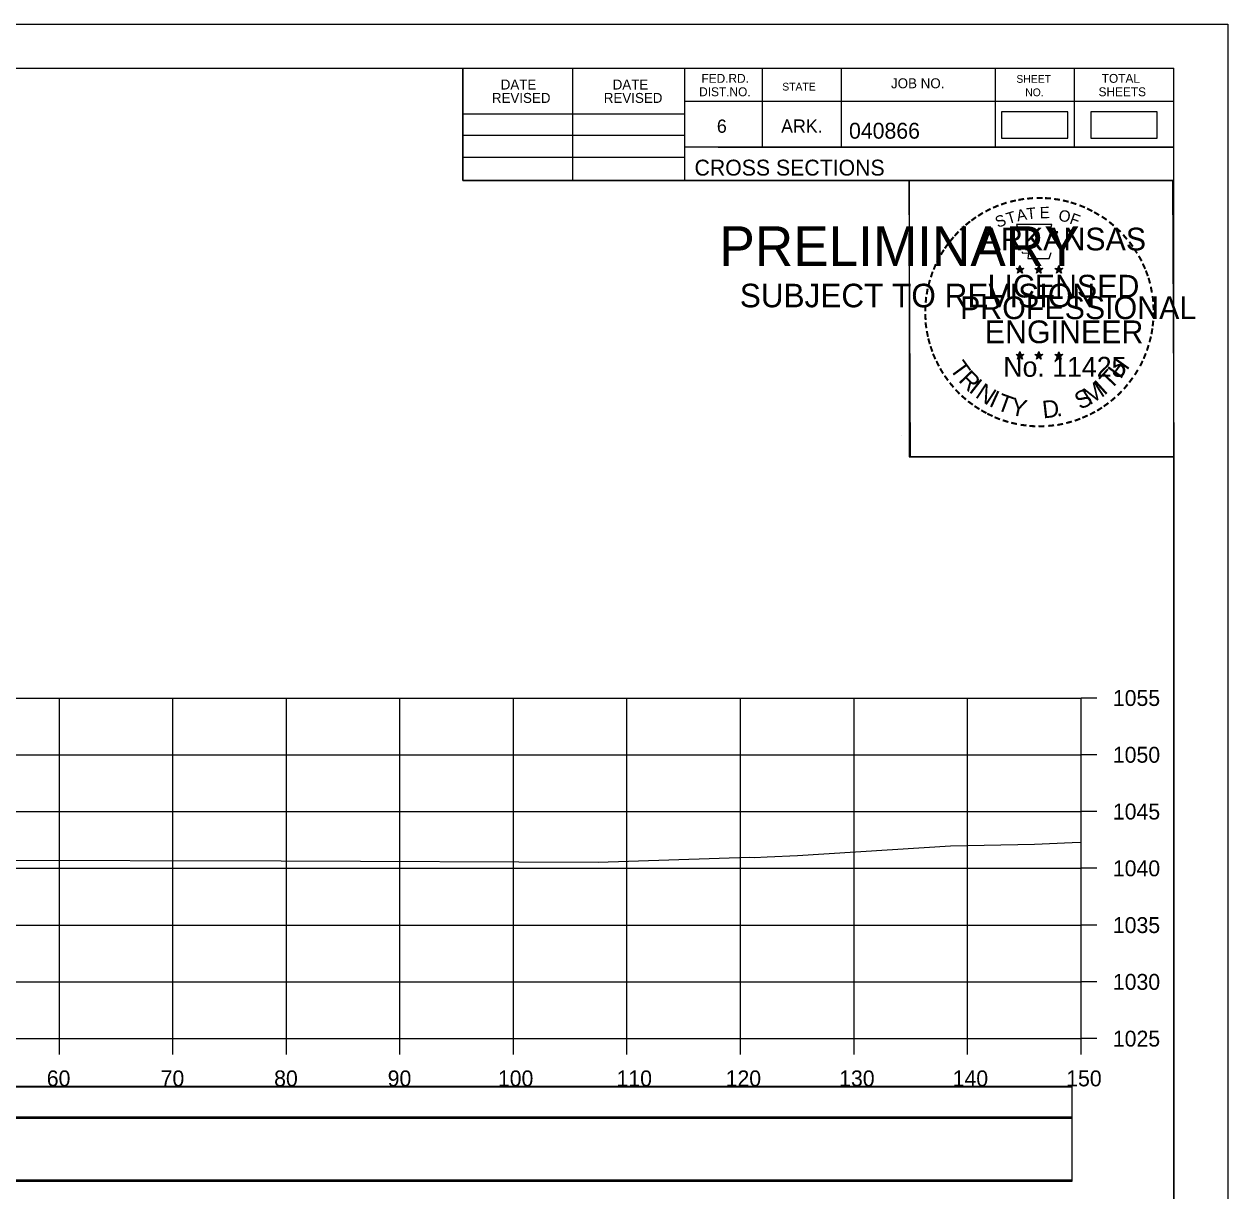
# Model space of a CAD drawing. Extents: x 1370565 to 1374448, y 301010 to 304637.
# Drawn here: x 1373425.7 to 1373531.7, y 301408.9 to 301511.7 of the extents above; entities that cross this region are included whole.
import ezdxf

# ---------------------------------------------------------------- set-up
doc = ezdxf.new("R2010")
doc.units = 0
for name, color, linetype in [('Default', 7, 'Continuous'), ('R_Axis', 7, 'Continuous'), ('R_Axis Annot', 7, 'Continuous'), ('R_Border', 7, 'Continuous'), ('R_Border PE', 7, 'Continuous'), ('R_Border Prem', 7, 'Continuous'), ('R_Drive', 7, 'Continuous'), ('R_Exist Surface', 7, 'Continuous'), ('R_Grid', 7, 'Continuous'), ('R_No Plot', 7, 'Continuous')]:
    doc.layers.add(name, color=color, linetype=linetype)

msp = doc.modelspace()

# ---------------------------------------------------------------- linework, layer by layer
at = {"layer": 'Default'}
for points in [[(1373511.81, 301501.6), (1373517.64, 301501.6), (1373517.64, 301503.91), (1373511.81, 301503.91)], [(1373219.61, 301415.34), (1373518.02, 301415.34), (1373518.02, 301418.04), (1373219.61, 301418.04)], [(1373219.61, 301409.76), (1373518.02, 301409.76), (1373518.02, 301415.28), (1373219.61, 301415.28)]]:
    msp.add_lwpolyline(points, close=True, dxfattribs=at)
at = {"layer": 'R_Axis'}
for p, q in [((1373518.81, 301422.3), (1373518.81, 301452.3)), ((1373520.21, 301452.3), (1373518.81, 301452.3)), ((1373520.21, 301447.3), (1373518.81, 301447.3)), ((1373520.21, 301442.3), (1373518.81, 301442.3)), ((1373520.21, 301437.3), (1373518.81, 301437.3)), ((1373520.21, 301432.3), (1373518.81, 301432.3)), ((1373520.21, 301427.3), (1373518.81, 301427.3)), ((1373218.81, 301422.3), (1373518.81, 301422.3)), ((1373428.81, 301420.9), (1373428.81, 301422.3)), ((1373438.81, 301420.9), (1373438.81, 301422.3)), ((1373448.81, 301420.9), (1373448.81, 301422.3)), ((1373458.81, 301420.9), (1373458.81, 301422.3)), ((1373468.81, 301420.9), (1373468.81, 301422.3)), ((1373478.81, 301420.9), (1373478.81, 301422.3)), ((1373488.81, 301420.9), (1373488.81, 301422.3)), ((1373498.81, 301420.9), (1373498.81, 301422.3)), ((1373508.81, 301420.9), (1373508.81, 301422.3)), ((1373518.81, 301420.9), (1373518.81, 301422.3)), ((1373520.21, 301422.3), (1373518.81, 301422.3))]:
    msp.add_line(p, q, dxfattribs=at)
at = {"layer": 'R_Border'}
for p, q in [((1373210.81, 301507.76), (1373526.99, 301507.76)), ((1373464.35, 301497.88), (1373464.35, 301507.76)), ((1373474.03, 301497.88), (1373474.03, 301507.76)), ((1373483.89, 301507.76), (1373483.89, 301497.88)), ((1373490.73, 301507.76), (1373490.73, 301500.82)), ((1373497.67, 301507.76), (1373497.67, 301500.82)), ((1373511.25, 301507.76), (1373511.25, 301500.82)), ((1373518.19, 301507.76), (1373518.19, 301500.82)), ((1373526.99, 301302.3), (1373526.99, 301507.76)), ((1373526.99, 301504.82), (1373483.89, 301504.82)), ((1373526.99, 301504.84), (1373526.99, 301504.84)), ((1373464.35, 301503.74), (1373483.89, 301503.74)), ((1373464.35, 301501.88), (1373483.89, 301501.88)), ((1373526.99, 301500.82), (1373483.89, 301500.82)), ((1373486.85, 301500.82), (1373526.99, 301500.82)), ((1373464.35, 301499.94), (1373483.89, 301499.94)), ((1373526.99, 301497.88), (1373464.35, 301497.88))]:
    msp.add_line(p, q, dxfattribs=at)
at = {"layer": 'R_Border PE'}
for p, q in [((1373513.08, 301490.13), (1373513.43, 301490.02)), ((1373513.08, 301490.13), (1373513.33, 301490.09)), ((1373513.08, 301490.13), (1373513.32, 301490.01)), ((1373513.21, 301489.73), (1373513.43, 301490.02)), ((1373513.21, 301489.73), (1373513.34, 301489.97)), ((1373513.21, 301489.73), (1373513.43, 301489.94)), ((1373513.43, 301490.39), (1373513.39, 301490.14)), ((1373513.43, 301490.02), (1373513.43, 301490.39)), ((1373513.43, 301490.39), (1373513.48, 301490.14)), ((1373513.78, 301490.13), (1373513.43, 301490.02)), ((1373513.64, 301489.73), (1373513.43, 301490.02)), ((1373513.64, 301489.73), (1373513.43, 301489.94)), ((1373513.78, 301490.13), (1373513.49, 301490.08)), ((1373513.64, 301489.73), (1373513.5, 301490.02)), ((1373513.78, 301490.13), (1373513.57, 301490.03)), ((1373514.75, 301490.13), (1373515.1, 301490.02)), ((1373514.75, 301490.13), (1373515, 301490.09)), ((1373514.75, 301490.13), (1373514.99, 301490.01)), ((1373514.88, 301489.73), (1373515.1, 301490.02)), ((1373514.88, 301489.73), (1373515.01, 301489.97)), ((1373514.88, 301489.73), (1373515.1, 301489.94)), ((1373515.1, 301490.39), (1373515.06, 301490.14)), ((1373515.1, 301490.02), (1373515.1, 301490.39)), ((1373515.1, 301490.39), (1373515.15, 301490.14)), ((1373515.45, 301490.13), (1373515.1, 301490.02)), ((1373515.31, 301489.73), (1373515.1, 301490.02)), ((1373515.31, 301489.73), (1373515.1, 301489.94)), ((1373515.45, 301490.13), (1373515.16, 301490.08)), ((1373515.31, 301489.73), (1373515.17, 301490.02)), ((1373515.45, 301490.13), (1373515.24, 301490.03)), ((1373516.51, 301490.12), (1373516.86, 301490.01)), ((1373516.51, 301490.12), (1373516.77, 301490.08)), ((1373516.51, 301490.12), (1373516.75, 301490)), ((1373516.65, 301489.71), (1373516.86, 301490.01)), ((1373516.65, 301489.71), (1373516.77, 301489.96)), ((1373516.65, 301489.71), (1373516.86, 301489.93)), ((1373516.86, 301490.38), (1373516.82, 301490.12)), ((1373516.86, 301490.01), (1373516.86, 301490.38)), ((1373516.86, 301490.38), (1373516.91, 301490.13)), ((1373517.21, 301490.12), (1373516.86, 301490.01)), ((1373517.08, 301489.71), (1373516.86, 301490.01)), ((1373517.08, 301489.71), (1373516.86, 301489.93)), ((1373517.21, 301490.12), (1373516.92, 301490.07)), ((1373517.08, 301489.71), (1373516.94, 301490)), ((1373517.21, 301490.12), (1373517.01, 301490.02)), ((1373513.08, 301482.56), (1373513.42, 301482.45)), ((1373513.08, 301482.56), (1373513.33, 301482.52)), ((1373513.08, 301482.56), (1373513.31, 301482.44)), ((1373513.21, 301482.15), (1373513.42, 301482.45)), ((1373513.21, 301482.15), (1373513.33, 301482.4)), ((1373513.21, 301482.15), (1373513.42, 301482.37)), ((1373513.42, 301482.81), (1373513.38, 301482.56)), ((1373513.42, 301482.45), (1373513.42, 301482.81)), ((1373513.42, 301482.81), (1373513.47, 301482.56)), ((1373513.77, 301482.56), (1373513.42, 301482.45)), ((1373513.64, 301482.15), (1373513.42, 301482.45)), ((1373513.64, 301482.15), (1373513.42, 301482.37)), ((1373513.77, 301482.56), (1373513.49, 301482.51)), ((1373513.64, 301482.15), (1373513.5, 301482.44)), ((1373513.77, 301482.56), (1373513.57, 301482.46)), ((1373514.74, 301482.56), (1373515.09, 301482.45)), ((1373514.74, 301482.56), (1373515, 301482.52)), ((1373514.74, 301482.56), (1373514.98, 301482.44)), ((1373514.88, 301482.15), (1373515.09, 301482.45)), ((1373514.88, 301482.15), (1373515, 301482.4)), ((1373514.88, 301482.15), (1373515.09, 301482.37)), ((1373515.09, 301482.81), (1373515.05, 301482.56)), ((1373515.09, 301482.45), (1373515.09, 301482.81)), ((1373515.09, 301482.81), (1373515.14, 301482.56)), ((1373515.44, 301482.56), (1373515.09, 301482.45)), ((1373515.31, 301482.15), (1373515.09, 301482.45)), ((1373515.31, 301482.15), (1373515.09, 301482.37)), ((1373515.44, 301482.56), (1373515.15, 301482.51)), ((1373515.31, 301482.15), (1373515.17, 301482.44)), ((1373515.44, 301482.56), (1373515.24, 301482.46)), ((1373516.51, 301482.55), (1373516.86, 301482.44)), ((1373516.51, 301482.55), (1373516.76, 301482.51)), ((1373516.51, 301482.55), (1373516.75, 301482.43)), ((1373516.64, 301482.14), (1373516.86, 301482.44)), ((1373516.64, 301482.14), (1373516.77, 301482.39)), ((1373516.64, 301482.14), (1373516.86, 301482.36)), ((1373516.86, 301482.8), (1373516.82, 301482.55)), ((1373516.86, 301482.44), (1373516.86, 301482.8)), ((1373516.86, 301482.8), (1373516.91, 301482.55)), ((1373517.21, 301482.55), (1373516.86, 301482.44)), ((1373517.07, 301482.14), (1373516.86, 301482.44)), ((1373517.07, 301482.14), (1373516.86, 301482.36)), ((1373517.21, 301482.55), (1373516.92, 301482.5)), ((1373517.07, 301482.14), (1373516.94, 301482.43)), ((1373517.21, 301482.55), (1373517, 301482.45))]:
    msp.add_line(p, q, dxfattribs=at)
for points in [[(1373513.12, 301494.01), (1373513.39, 301493.18)], [(1373516.63, 301493.09), (1373516.77, 301493.37), (1373516.09, 301493.35), (1373516.24, 301494.01), (1373513.12, 301494.01)], [(1373513.61, 301491.59), (1373513.61, 301491.5), (1373514.18, 301491.48), (1373514.12, 301491.01), (1373515.99, 301491.01), (1373516.19, 301491.55)], [(1373513.43, 301490.39), (1373513.64, 301489.73), (1373513.08, 301490.13), (1373513.78, 301490.13), (1373513.21, 301489.73), (1373513.43, 301490.39)], [(1373515.1, 301490.39), (1373515.31, 301489.73), (1373514.75, 301490.13), (1373515.45, 301490.13), (1373514.88, 301489.73), (1373515.1, 301490.39)], [(1373516.86, 301490.38), (1373517.08, 301489.71), (1373516.51, 301490.12), (1373517.21, 301490.12), (1373516.65, 301489.71), (1373516.86, 301490.38)], [(1373513.42, 301482.81), (1373513.64, 301482.15), (1373513.08, 301482.56), (1373513.77, 301482.56), (1373513.21, 301482.15), (1373513.42, 301482.81)], [(1373515.09, 301482.81), (1373515.31, 301482.15), (1373514.74, 301482.56), (1373515.44, 301482.56), (1373514.88, 301482.15), (1373515.09, 301482.81)], [(1373516.86, 301482.8), (1373517.07, 301482.14), (1373516.51, 301482.55), (1373517.21, 301482.55), (1373516.64, 301482.14), (1373516.86, 301482.8)]]:
    msp.add_lwpolyline(points, dxfattribs=at)
for centre, radius in [((1373513.43, 301490.02), 0.172), ((1373513.43, 301490.02), 0.145), ((1373513.43, 301490.02), 0.116), ((1373513.43, 301490.02), 0.0991), ((1373513.43, 301490.02), 0.0747), ((1373513.43, 301490.02), 0.0495), ((1373513.43, 301490.02), 0.0296), ((1373515.1, 301490.02), 0.172), ((1373515.1, 301490.02), 0.145), ((1373515.1, 301490.02), 0.116), ((1373515.1, 301490.02), 0.0991), ((1373515.1, 301490.02), 0.0747), ((1373515.1, 301490.02), 0.0495), ((1373515.1, 301490.02), 0.0296), ((1373516.86, 301490.01), 0.172), ((1373516.86, 301490.01), 0.145), ((1373516.86, 301490.01), 0.116), ((1373516.86, 301490.01), 0.0991), ((1373516.86, 301490.01), 0.0747), ((1373516.86, 301490.01), 0.0495), ((1373516.86, 301490.01), 0.0296), ((1373513.42, 301482.45), 0.172), ((1373513.42, 301482.45), 0.145), ((1373513.42, 301482.45), 0.116), ((1373513.42, 301482.45), 0.0991), ((1373513.42, 301482.45), 0.0747), ((1373513.42, 301482.45), 0.0495), ((1373513.42, 301482.45), 0.0296), ((1373515.09, 301482.45), 0.172), ((1373515.09, 301482.45), 0.145), ((1373515.09, 301482.45), 0.116), ((1373515.09, 301482.45), 0.0991), ((1373515.09, 301482.45), 0.0747), ((1373515.09, 301482.45), 0.0495), ((1373515.09, 301482.45), 0.0296), ((1373516.86, 301482.44), 0.172), ((1373516.86, 301482.44), 0.145), ((1373516.86, 301482.44), 0.116), ((1373516.86, 301482.44), 0.0991), ((1373516.86, 301482.44), 0.0747), ((1373516.86, 301482.44), 0.0495), ((1373516.86, 301482.44), 0.0296)]:
    msp.add_circle(centre, radius, dxfattribs=at)
at = {"layer": 'R_Drive'}
for points in [[(1373519.68, 301501.61), (1373525.51, 301501.61), (1373525.51, 301503.92), (1373519.68, 301503.92)], [(1373219.61, 301415.39), (1373518.02, 301415.39), (1373518.02, 301418.1), (1373219.61, 301418.1)], [(1373219.61, 301409.87), (1373518.02, 301409.87), (1373518.02, 301415.39), (1373219.61, 301415.39)]]:
    msp.add_lwpolyline(points, close=True, dxfattribs=at)
at = {"layer": 'R_Exist Surface'}
msp.add_lwpolyline([(1373304.34, 301436.57), (1373342.67, 301437.61), (1373353.33, 301435.92), (1373354.89, 301435.65), (1373359.09, 301436.44), (1373372.67, 301438.99), (1373374.17, 301439.03), (1373383.25, 301439.29), (1373391.86, 301439.22), (1373393.43, 301439.2), (1373397.72, 301438.66), (1373412.1, 301436.72), (1373414.24, 301437.01), (1373421.68, 301438.02), (1373448.35, 301437.96), (1373476.27, 301437.85), (1373489.59, 301438.27), (1373490.01, 301438.26), (1373491.15, 301438.32), (1373493.83, 301438.43), (1373507.3, 301439.28), (1373514.72, 301439.44), (1373518.02, 301439.57), (1373518.81, 301439.61)], dxfattribs=at)
at = {"layer": 'R_Grid'}
for p, q in [((1373218.81, 301452.3), (1373518.81, 301452.3)), ((1373428.81, 301422.3), (1373428.81, 301452.3)), ((1373438.81, 301422.3), (1373438.81, 301452.3)), ((1373448.81, 301422.3), (1373448.81, 301452.3)), ((1373458.81, 301422.3), (1373458.81, 301452.3)), ((1373468.81, 301422.3), (1373468.81, 301452.3)), ((1373478.81, 301422.3), (1373478.81, 301452.3)), ((1373488.81, 301422.3), (1373488.81, 301452.3)), ((1373498.81, 301422.3), (1373498.81, 301452.3)), ((1373508.81, 301422.3), (1373508.81, 301452.3)), ((1373518.81, 301422.3), (1373518.81, 301452.3)), ((1373218.81, 301447.3), (1373518.81, 301447.3)), ((1373218.81, 301442.3), (1373518.81, 301442.3)), ((1373218.81, 301437.3), (1373518.81, 301437.3)), ((1373218.81, 301432.3), (1373518.81, 301432.3)), ((1373218.81, 301427.3), (1373518.81, 301427.3)), ((1373218.81, 301422.3), (1373518.81, 301422.3))]:
    msp.add_line(p, q, dxfattribs=at)
at = {"layer": 'R_No Plot'}
for p, q in [((1373198.41, 301511.65), (1373531.75, 301511.65)), ((1373503.03, 301475.42), (1373503.03, 301475.42))]:
    msp.add_line(p, q, dxfattribs=at)
for points in [[(1373198.41, 301511.65), (1373531.75, 301511.65), (1373531.75, 301298.32), (1373198.41, 301298.32)], [(1373444.73, 301507.76), (1373464.35, 301507.76), (1373464.35, 301497.88), (1373480.47, 301497.88), (1373503.67, 301497.88), (1373503.67, 301473.55), (1373526.99, 301473.55), (1373526.99, 301302.3), (1373210.81, 301302.3), (1373210.81, 301507.76)], [(1373503.67, 301497.88), (1373526.87, 301497.88), (1373526.99, 301473.55), (1373503.79, 301473.55)]]:
    msp.add_lwpolyline(points, close=True, dxfattribs=at)

# ---------------------------------------------------------------- texts
at = {"layer": 'R_Axis Annot'}
for s, p in [('1055', (1373521.61, 301451.6)), ('1050', (1373521.61, 301446.6)), ('1045', (1373521.61, 301441.6)), ('1040', (1373521.61, 301436.6)), ('1035', (1373521.61, 301431.6)), ('1030', (1373521.61, 301426.6)), ('1025', (1373521.61, 301421.6)), ('60', (1373427.7, 301418.1)), ('70', (1373437.73, 301418.1)), ('80', (1373447.73, 301418.1)), ('90', (1373457.73, 301418.1)), ('100', (1373467.44, 301418.1)), ('110', (1373477.89, 301418.1)), ('120', (1373487.5, 301418.1)), ('130', (1373497.5, 301418.1)), ('140', (1373507.5, 301418.1)), ('150', (1373517.5, 301418.1))]:
    msp.add_text(s, height=1.4, dxfattribs=at).set_placement(p)
at = {"layer": 'R_Border'}
for s, height, p in [('DATE', 0.879, (1373467.69, 301505.89)), ('DATE', 0.879, (1373477.55, 301505.89)), ('FED.RD.', 0.782, (1373485.37, 301506.48)), ('JOB NO.', 0.879, (1373502.07, 301506)), ('SHEET', 0.684, (1373513.11, 301506.48)), ('TOTAL', 0.782, (1373520.63, 301506.48)), ('REVISED', 0.879, (1373466.91, 301504.71)), ('REVISED', 0.879, (1373476.77, 301504.71)), ('DIST.NO.', 0.782, (1373485.17, 301505.3)), ('STATE', 0.684, (1373492.49, 301505.8)), ('NO.', 0.684, (1373513.89, 301505.3)), ('SHEETS', 0.782, (1373520.35, 301505.3)), ('6', 1.17, (1373486.73, 301502.08)), ('ARK.', 1.172, (1373492.39, 301502.08)), ('040866', 1.4, (1373498.37, 301501.56)), ('CROSS SECTIONS', 1.4, (1373484.76, 301498.31))]:
    msp.add_text(s, height=height, rotation=360, dxfattribs=at).set_placement(p)
at = {"layer": 'R_Border PE'}
for s, height, rotation, p in [('-', 1.6, 13.6301, (1373512.62, 301495.38)), ('-', 1.6, 10.2193, (1373513.3, 301495.54)), ('-', 1.6, 5.8968, (1373514.03, 301495.65)), ('-', 1.6, 0.1862, (1373514.8, 301495.72)), ('-', 1.6, 357.743, (1373515.52, 301495.71)), ('-', 1.6, 352.1617, (1373516.26, 301495.65)), ('-', 1.6, 347.2049, (1373516.98, 301495.54)), ('-', 1.6, 342.3362, (1373517.62, 301495.39)), ('-', 1.6, 34.0636, (1373510, 301494.18)), ('-', 1.6, 28.7918, (1373510.6, 301494.55)), ('-', 1.6, 24.3072, (1373511.23, 301494.87)), ('-', 1.6, 19.1761, (1373511.87, 301495.14)), ('T', 1, 16.4036, (1373512.39, 301494.02)), ('A', 1, 11.2132, (1373513.22, 301494.27)), ('T', 1, 6.0228, (1373514.06, 301494.44)), ('E', 1, 0.8323, (1373515.17, 301494.55)), ('O', 1, 350.4515, (1373516.77, 301494.34)), ('F', 1, 340.0707, (1373517.73, 301494.11)), ('-', 1.6, 337.8551, (1373518.35, 301495.16)), ('-', 1.6, 334.1211, (1373518.98, 301494.89)), ('-', 1.6, 329.6409, (1373519.56, 301494.61)), ('-', 1.6, 42.9622, (1373508.52, 301492.99)), ('-', 1.6, 38.9507, (1373508.95, 301493.41)), ('-', 1.6, 36.2317, (1373509.43, 301493.79)), ('S', 1, 21.594, (1373511.48, 301493.69)), ('-', 1.6, 325.8627, (1373520.21, 301494.25)), ('-', 1.6, 320.5297, (1373520.82, 301493.82)), ('-', 1.6, 50.6142, (1373507.67, 301492.03)), ('-', 1.6, 48.423, (1373508.07, 301492.51)), ('ARKANSAS', 2, 360, (1373509.97, 301491.72)), ('-', 1.6, 315.5786, (1373521.42, 301493.33)), ('-', 1.6, 309.8797, (1373521.98, 301492.78)), ('-', 1.6, 58.0706, (1373506.93, 301490.93)), ('-', 1.6, 54.2325, (1373507.25, 301491.46)), ('-', 1.6, 306.6522, (1373522.51, 301492.18)), ('-', 1.4, 303.6753, (1373523, 301491.61)), ('-', 1.6, 62.8713, (1373506.62, 301490.32)), ('-', 1.6, 299.6684, (1373523.31, 301491.01)), ('-', 1.6, 72.3945, (1373506.14, 301489.08)), ('-', 1.6, 67.7743, (1373506.36, 301489.71)), ('DWB', 0.01, 360, (1373513.42, 301490.02)), ('DWB', 0.01, 360, (1373515.09, 301490.02)), ('DWB', 0.01, 360, (1373516.85, 301490.01)), ('-', 1.6, 294.6628, (1373523.64, 301490.39)), ('-', 1.6, 290.5728, (1373523.9, 301489.82)), ('-', 1.6, 75.461, (1373505.94, 301488.37)), ('LICENSED', 2, 360, (1373510.57, 301487.57)), ('-', 1.6, 285.1233, (1373524.13, 301489.24)), ('-', 1.6, 85.1863, (1373505.73, 301486.96)), ('-', 1.6, 81.2013, (1373505.81, 301487.65)), ('PROFESSIONAL', 2, 360, (1373508.15, 301485.67)), ('-', 1.6, 280.5493, (1373524.33, 301488.5)), ('-', 1.6, 276.5962, (1373524.49, 301487.73)), ('-', 1.6, 89.0622, (1373505.71, 301486.26)), ('-', 1.6, 274.3301, (1373524.55, 301487.01)), ('-', 1.6, 94.1959, (1373505.74, 301485.54)), ('ENGINEER', 2, 360, (1373510.33, 301483.55)), ('-', 1.6, 263.5172, (1373524.57, 301485.71)), ('-', 1.6, 269.9407, (1373524.59, 301486.37)), ('-', 1.6, 98.9479, (1373505.81, 301484.87)), ('-', 1.6, 101.7149, (1373505.95, 301484.14)), ('-', 1.6, 260.9953, (1373524.5, 301485.05)), ('-', 1.6, 105.4578, (1373506.11, 301483.54)), ('-', 1.6, 109.0874, (1373506.33, 301482.91)), ('-', 1.6, 252.8681, (1373524.2, 301483.66)), ('-', 1.6, 255.7626, (1373524.39, 301484.38)), ('-', 1.6, 114.0643, (1373506.58, 301482.31)), ('No. 11425', 1.757, 360, (1373511.96, 301480.59)), ('DWB', 0.01, 360, (1373513.41, 301482.44)), ('DWB', 0.01, 360, (1373515.08, 301482.44)), ('DWB', 0.01, 360, (1373516.85, 301482.43)), ('H', 1.54, 54.6088, (1373522.3, 301480.32)), ('-', 1.6, 247.8887, (1373523.98, 301482.98)), ('-', 1.6, 115.7289, (1373506.89, 301481.7)), ('-', 1.6, 120.4471, (1373507.24, 301481.11)), ('T', 1.54, 306.0406, (1373507.18, 301481.29)), ('R', 1.54, 314.005, (1373507.95, 301480.24)), ('T', 1.54, 46.6444, (1373521.41, 301479.38)), ('-', 1.6, 239.0712, (1373523.33, 301481.6)), ('-', 1.6, 244.6197, (1373523.72, 301482.35)), ('-', 1.6, 125.8934, (1373507.65, 301480.55)), ('-', 1.6, 130.7181, (1373508.11, 301480)), ('I', 1.54, 321.9694, (1373508.85, 301479.31)), ('M', 1.54, 32.6563, (1373519.57, 301478.06)), ('I', 1.54, 42.1136, (1373520.85, 301478.9)), ('-', 1.6, 233.8452, (1373522.92, 301480.95)), ('-', 1.6, 134.2238, (1373508.62, 301479.45)), ('N', 1.54, 326.5002, (1373509.41, 301478.84)), ('I', 1.54, 335.3603, (1373510.62, 301478.05)), ('T', 1.54, 339.8912, (1373511.28, 301477.72)), ('S', 1.54, 26.9312, (1373518.73, 301477.65)), ('-', 1.6, 225.7653, (1373522.01, 301479.82)), ('-', 1.6, 231.2538, (1373522.49, 301480.38)), ('-', 1.6, 138.9338, (1373509.15, 301478.99)), ('-', 1.6, 144.6463, (1373509.71, 301478.58)), ('-', 1.6, 148.0898, (1373510.27, 301478.21)), ('Y', 1.54, 347.8556, (1373512.5, 301477.28)), ('D', 1.54, 6.3969, (1373515.48, 301476.92)), ('-', 1.6, 215.7363, (1373520.94, 301478.84)), ('-', 1.6, 221.0851, (1373521.49, 301479.31)), ('-', 1.6, 151.5704, (1373510.85, 301477.89)), ('-', 1.6, 154.6002, (1373511.37, 301477.64)), ('-', 1.6, 158.5612, (1373511.99, 301477.38)), ('.', 1.54, 13.7642, (1373516.68, 301477.05)), ('-', 1.6, 200.7184, (1373518.61, 301477.51)), ('-', 1.6, 204.2516, (1373519.23, 301477.79)), ('-', 1.6, 207.3568, (1373519.85, 301478.1)), ('-', 1.6, 212.2491, (1373520.41, 301478.45)), ('-', 1.6, 162.7983, (1373512.68, 301477.17)), ('-', 1.6, 167.5555, (1373513.39, 301477.01)), ('-', 1.6, 173.1155, (1373514.17, 301476.9)), ('-', 1.6, 176.5183, (1373514.91, 301476.84)), ('-', 1.6, 181.5918, (1373515.66, 301476.86)), ('-', 1.6, 185.8167, (1373516.47, 301476.94)), ('-', 1.6, 191.2858, (1373517.2, 301477.07)), ('-', 1.6, 195.4743, (1373517.93, 301477.27))]:
    msp.add_text(s, height=height, rotation=rotation, dxfattribs=at).set_placement(p)
at = {"layer": 'R_Border Prem'}
for s, height, p in [('PRELIMINARY', 3.5, (1373486.95, 301490.34)), ('DWB', 0.01, (1373487.69, 301492.19)), ('SUBJECT TO REVISION', 2.0751, (1373488.75, 301486.71))]:
    msp.add_text(s, height=height, rotation=360, dxfattribs=at).set_placement(p)

doc.saveas('drawing.dxf')
